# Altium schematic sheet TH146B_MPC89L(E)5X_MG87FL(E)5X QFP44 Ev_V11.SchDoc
size 279 x 193 mm; PageSetup: Record=PageOptions|CenterHorizontal=True|CenterVertical=True|PrintScale=1.02|XCorrection=1.00|YCorrection=1.00|PrintKind=0|BorderSize=5000000|LeftOffset=0|BottomOffset=0|Orientation=2|PaperLength=1000|PaperWidth=1000|Scale=100|PaperSource=7|PrintQuality=-4|MediaType=1|DitherType=10|PaperKind=A4 (210 x 297 mm)|PrintScaleMode=1
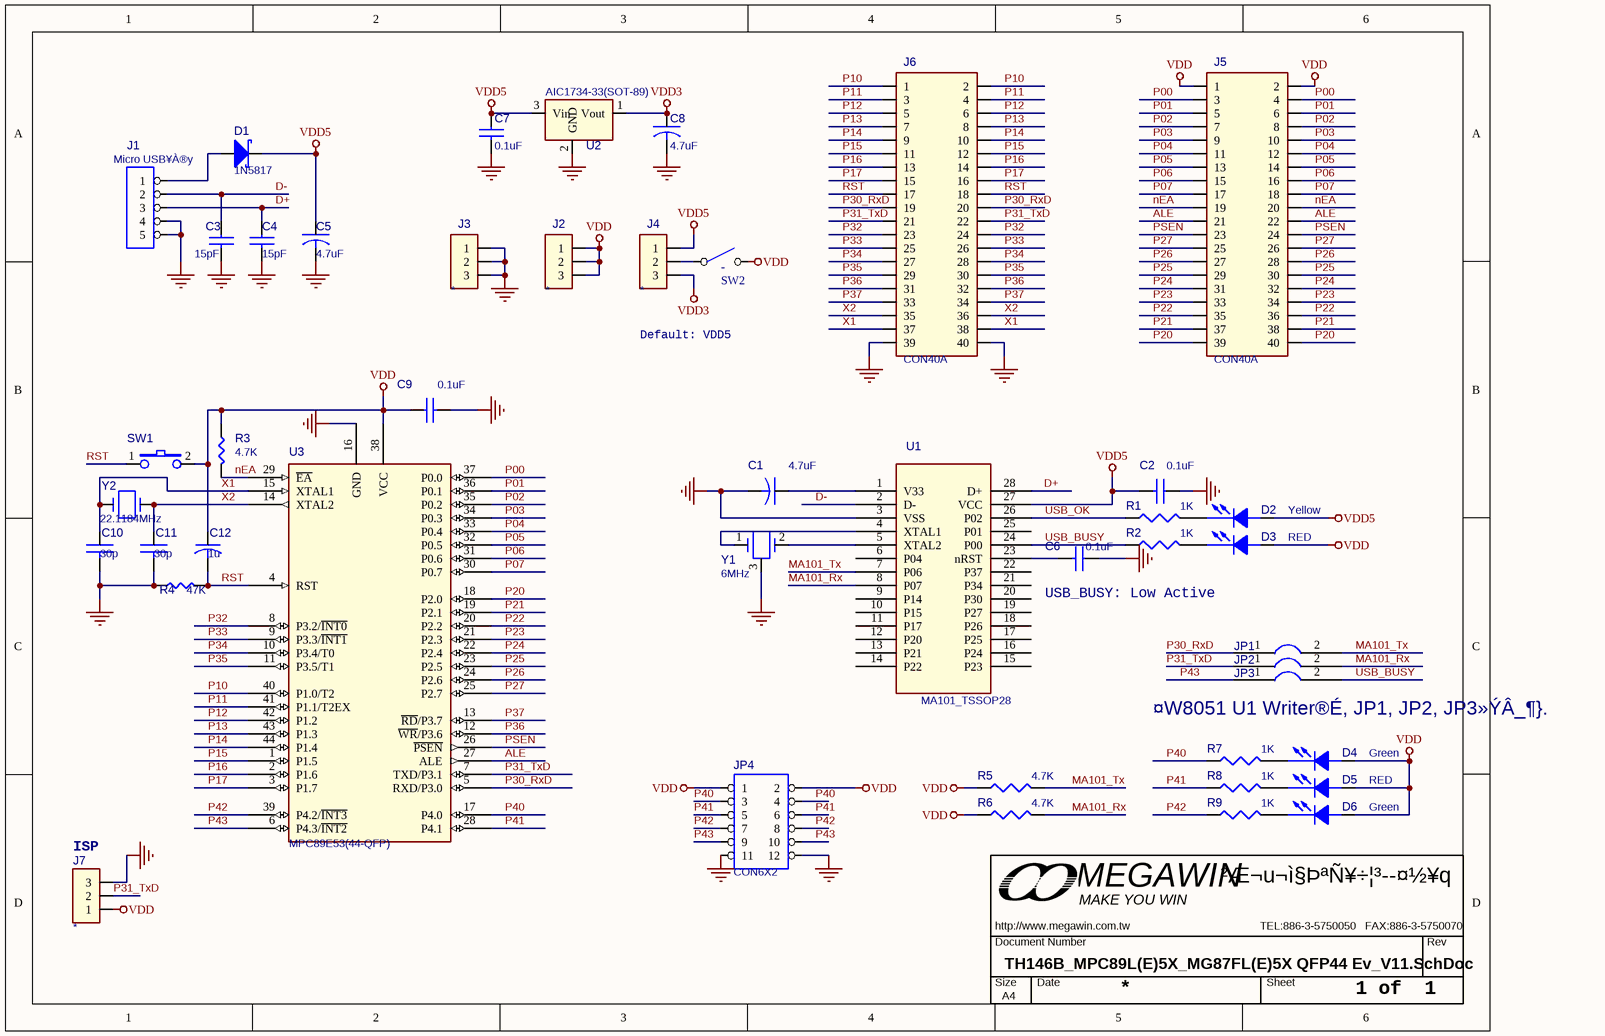
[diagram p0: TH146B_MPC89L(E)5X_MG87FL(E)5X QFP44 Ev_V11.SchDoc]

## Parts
C1  4.7uF  [0805C]
C2  0.1uF  [0805C]
C3  15pF  [0805C]
C4  15pF  [0805C]
C5  4.7uF  [1206C]
C6  0.1uF  [0805C]
C7  0.1uF  [0805C]
C8  4.7uF  [0805C]
C9  0.1uF  [0805C]
C10  30p  [0805C]
C11  30p  [0805C]
C12  1u  [0805C]
D1  1N5817  [D5817_SMD_1]
D2  Yellow  [0805D]
D3  RED  [0805D]
D4  Green  [0805D]
D5  RED  [0805D]
D6  Green  [0805D]
J1  Micro USB¥À®y  [JACK_USB_SMD290X220P065]
J2  *  [PS3P254]
J3  *  [PS3P254]
J4  *  [JUMP3_SMD]
J5  CON40A  [PS20X2P254]
J6  CON40A  [PS20X2P254]
J7  *  [PS3P254f_90]
JP1  JUMPER2  [PS2P254]  (value not drawn)
JP2  JUMPER2  [PS2P254]  (value not drawn)
JP3  JUMPER2  [PS2P254]  (value not drawn)
JP4  CON6X2  [PS6X2P254]
MW1  OrgName: ²Æ¬u¬ì§ÞªÑ¥÷¦³­­¤½¥q  OrgAddr1: MEGAWIN  OrgAddr3: TEL:886-3-5750050   FAX:886-3-5750070  Page Size: A4  [MEGAWIN_T]  (hidden comment: MW-A4)  (no BOM)
R1  1K  [0805R]
R2  1K  [0805R]
R3  4.7K  [0805R]
R4  47K  [0805R]
R5  4.7K  [0805R]
R6  4.7K  [0805R]
R7  1K  [0805R]
R8  1K  [0805R]
R9  1K  [0805R]
SW1  SW TACT-SPST  [SW_T_2P]  (value not drawn)
SW2  -  [DIP2_SW]
U1  MA101_TSSOP28  [TSSOP28_170P065]
U2  AIC1734-33(SOT-89)  [SOT89]
U3  MPC89E53(44-QFP)  [QFP44_10X10P080]
Y1  6MHz  [X3P]
Y2  22.1184MHz  [X49U]

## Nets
GND_POWER: C1.2 C2.1 C3.2 C4.2 C5.2 C6.1 C7.2 C8.2 C9.2 C10.2 C11.2 J1.4 J1.5 J3.1 J3.2 J3.3 J6.39 J6.40 J7.3 JP4.11 JP4.12 R4.1 U1.3(VSS) U2.2(GND) U3.16(GND) Y1.3
VDD: C9.1 C12.1(POS) D3.1(ANODE) D4.1(ANODE) D5.1(ANODE) D6.1(ANODE) J2.1 J2.2 J2.3 J5.1 J5.2 J7.1 JP4.1 JP4.2 R3.1 R5.1 R6.1 SW1.2 SW2.2(NO) U3.38(VCC)
VDD3: C8.1 J4.3 U2.1(Vout)
VDD5: C2.2 C5.1 C7.1 D1.2(K) D2.1(ANODE) J4.1 U1.27(VCC) U2.3(Vin)
ALE: J5.21 J5.22 U3.27(ALE)
D+: C4.1 J1.3 U1.28(D+)
D-: C3.1 J1.2 U1.2(D-)
MA101_Rx: JP2.2 R6.2 U1.8(P07)
MA101_Tx: JP1.2 R5.2 U1.7(P06)
nEA: J5.19 J5.20 R3.2 U3.29(~{EA})
P00: J5.3 J5.4 U3.37(P0.0)
P01: J5.5 J5.6 U3.36(P0.1)
P02: J5.7 J5.8 U3.35(P0.2)
P03: J5.9 J5.10 U3.34(P0.3)
P04: J5.11 J5.12 U3.33(P0.4)
P05: J5.13 J5.14 U3.32(P0.5)
P06: J5.15 J5.16 U3.31(P0.6)
P07: J5.17 J5.18 U3.30(P0.7)
P10: J6.1 J6.2 U3.40(P1.0/T2)
P11: J6.3 J6.4 U3.41(P1.1/T2EX)
P12: J6.5 J6.6 U3.42(P1.2)
P13: J6.7 J6.8 U3.43(P1.3)
P14: J6.9 J6.10 U3.44(P1.4)
P15: J6.11 J6.12 U3.1(P1.5)
P16: J6.13 J6.14 U3.2(P1.6)
P17: J6.15 J6.16 U3.3(P1.7)
P20: J5.39 J5.40 U3.18(P2.0)
P21: J5.37 J5.38 U3.19(P2.1)
P22: J5.35 J5.36 U3.20(P2.2)
P23: J5.33 J5.34 U3.21(P2.3)
P24: J5.31 J5.32 U3.22(P2.4)
P25: J5.29 J5.30 U3.23(P2.5)
P26: J5.27 J5.28 U3.24(P2.6)
P27: J5.25 J5.26 U3.25(P2.7)
P30_RxD: J6.19 J6.20 JP1.1 U3.5(RXD/P3.0)
P31_TxD: J6.21 J6.22 J7.2 JP2.1 U3.7(TXD/P3.1)
P32: J6.23 J6.24 U3.8(P3.2/~{INT0})
P33: J6.25 J6.26 U3.9(P3.3/~{INT1})
P34: J6.27 J6.28 U3.10(P3.4/T0)
P35: J6.29 J6.30 U3.11(P3.5/T1)
P36: J6.31 J6.32 U3.12(~{WR}/P3.6)
P37: J6.33 J6.34 U3.13(~{RD}/P3.7)
P40: JP4.3 JP4.4 R7.1 U3.17(P4.0)
P41: JP4.5 JP4.6 R8.1 U3.28(P4.1)
P42: JP4.7 JP4.8 R9.1 U3.39(P4.2/~{INT3})
P43: JP3.1 JP4.9 JP4.10 U3.6(P4.3/~{INT2})
PSEN: J5.23 J5.24 U3.26(~{PSEN})
RST: C12.2(NEG) J6.17 J6.18 R4.2 SW1.1 U3.4(RST)
USB_BUSY: JP3.2 R2.1 U1.24(P00)
USB_OK: R1.1 U1.26(P02)
X1: C10.1 J6.37 J6.38 U3.15(XTAL1) Y2.1
X2: C11.1 J6.35 J6.36 U3.14(XTAL2) Y2.2
NetC1_1: C1.1 U1.1(V33)
NetC6_2: C6.2 U1.23(nRST)
NetD1_1: D1.1(A) J1.1
NetD2_2: D2.2(CATHODE) R1.2
NetD3_2: D3.2(CATHODE) R2.2
NetD4_2: D4.2(CATHODE) R7.2
NetD5_2: D5.2(CATHODE) R8.2
NetD6_2: D6.2(CATHODE) R9.2
NetJ4_2: J4.2 SW2.1(COMMON)
NetU1_4: U1.4(XTAL1) Y1.1
NetU1_5: U1.5(XTAL2) Y1.2

Not connected (* = marked no-connect by the designer): U1 6(P04) 9(P14) 10(P15) 11(P17) 12(P20) 13(P21) 14(P22) 15(P23) 16(P24) 17(P25) 18(P26) 19(P27) 20(P30) 21(P34) 22(P37) 25(P01)

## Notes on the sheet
- Default: VDD5
- USB_BUSY: Low Active
- ¤W8051 U1 Writer®É, JP1, JP2, JP3»ÝÂ_¶}.
- (near J7) ISP
- 1 of  1

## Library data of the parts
C1 C5 C8 = CAP
C2-C4 C6 C7 C9 = CAP NP
C10 C11 = C NP
C12 = C
D1 = DIODE_ZD: Schottky Diode
D2-D6 = LED
J1 = CON5: Connector
J2-J4 J7 = CON3
R1 R2 R5-R9 = R_Dup1
R3 R4 = R
SW2 = SW-2
U2 = AIC1734-33(SOT-89)_0
U3 = MPC89L53(44-QFP)
Y1 = CRYSTAL_RC
Y2 = CRYSTAL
